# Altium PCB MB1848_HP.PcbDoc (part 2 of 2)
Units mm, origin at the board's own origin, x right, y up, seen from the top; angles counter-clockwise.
Board outline 61.5 x 34 mm, 4 copper layers (Top Layer, MidLayer 1, MidLayer 2, Bottom Layer), stack 1.035 mm thick; 124 components, 86 nets, 341 pads, 1082 vias.
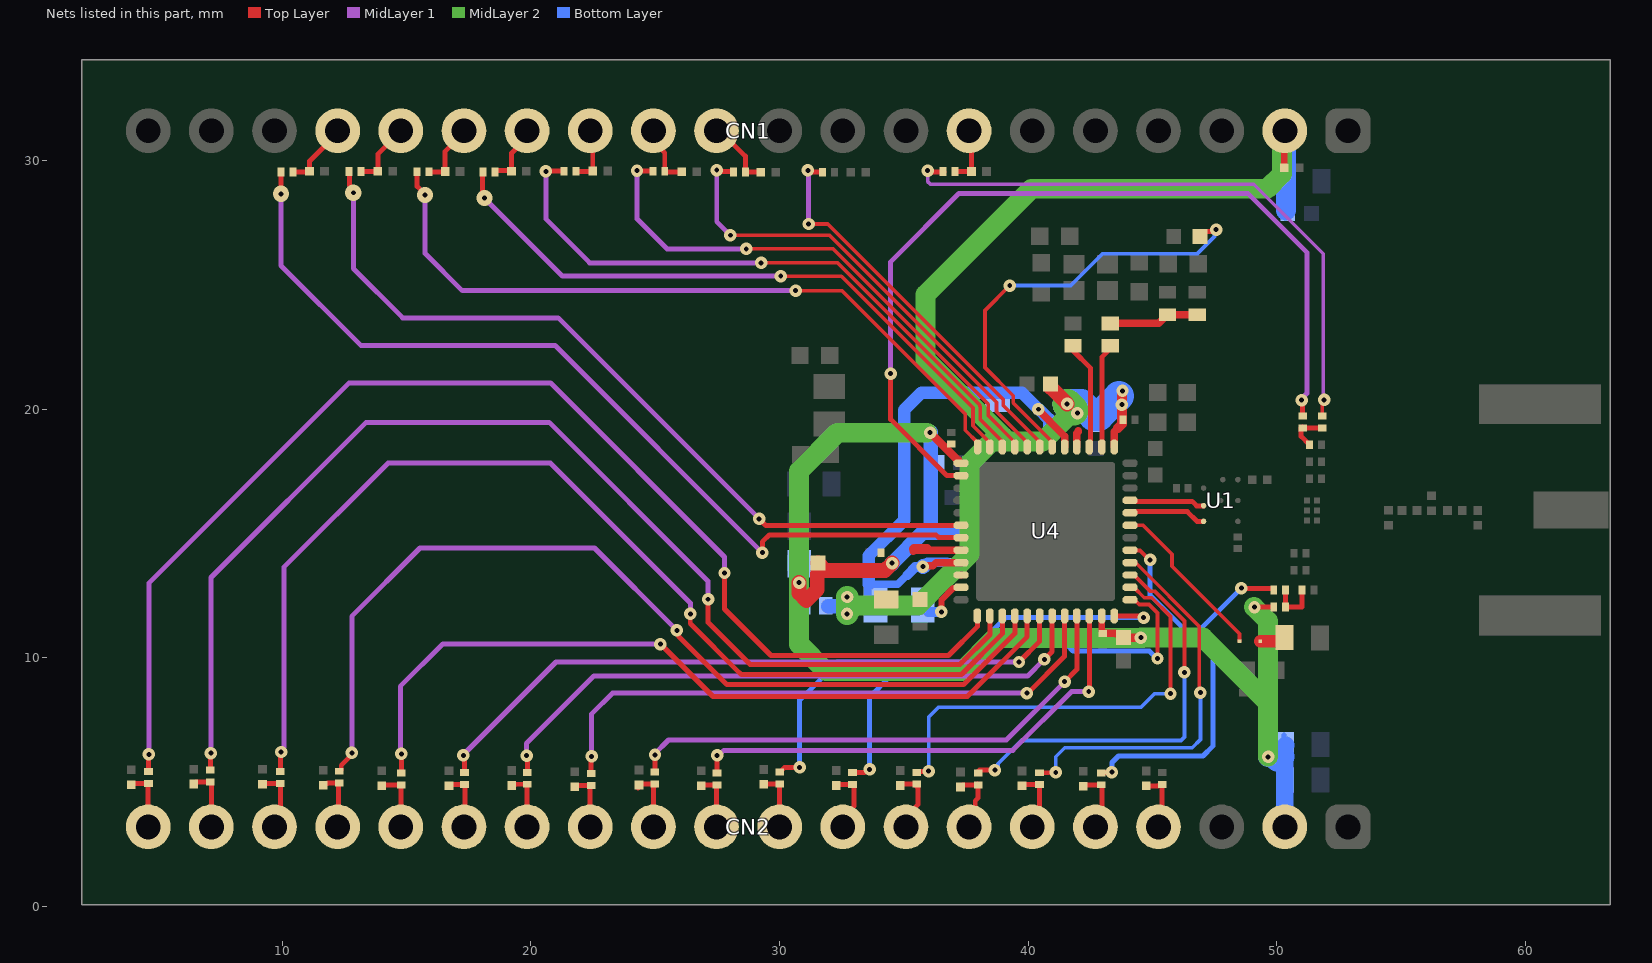
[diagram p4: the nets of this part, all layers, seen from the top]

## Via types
v1: diameter 0.5, hole 0.2, Top Layer to Bottom Layer, 395 vias
v2: diameter 0.65, hole 0.2, Top Layer to Bottom Layer, 321 vias
v3: diameter 0.6, hole 0.2, Top Layer to Bottom Layer, 291 vias
v4: diameter 0.4, hole 0.2, Top Layer to Bottom Layer, tented both sides, 75 vias

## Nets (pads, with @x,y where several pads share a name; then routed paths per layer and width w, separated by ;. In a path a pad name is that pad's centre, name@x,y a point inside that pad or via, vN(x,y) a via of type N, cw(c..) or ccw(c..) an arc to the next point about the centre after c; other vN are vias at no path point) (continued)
NetC202_1: C202.1 CN1.11 R202.2 | length 3.2
  Top Layer w0.2: CN1.11@27.413,31.109 27.683,31.109 28.62,30.172 R202.2@28.62,29.533 29.277,29.533 C202.1@29.284,29.526
  MidLayer 1 w0.2: CN1.11@27.463,30.896 CN1.11@27.463,31.192
NetC203_1: C203.1 CN1.12 R203.2 | length 3.1
  Top Layer w0.2: CN1.12@24.894,31.223 24.894,30.788 25.38,30.302 R203.2@25.38,29.568 ; R203.2@25.362,29.586 R203.2@25.38,29.568 ; R203.2@25.38,29.559 R203.2@25.38,29.568 ; C203.1@26.065,29.542 25.406,29.542 R203.2@25.38,29.568
  MidLayer 1 w0.2: CN1.12@24.923,30.718 CN1.12@24.923,31.192
NetC204_1: C204.1 CN1.13 R204.2 | length 2.3
  Top Layer w0.2: R204.2@21.814,29.563 22.502,29.563 C204.1@22.519,29.58 ; CN1.13@22.363,31.103 22.485,30.982 C204.1@22.485,29.577
NetC205_1: C205.1 CN1.14 R205.2 | length 2.5
  Top Layer w0.2: R205.2@18.552,29.537 18.552,29.544 18.592,29.584 C205.1@19.215,29.584 ; C205.1@19.215,29.563 C205.1@19.215,29.584 ; C205.1@19.253,29.584 C205.1@19.215,29.584 ; CN1.14@19.863,31.081 19.863,30.936 19.215,30.288 C205.1@19.215,29.584
NetC206_1: C206.1 CN1.15 R206.2 | length 2.5
  Top Layer w0.2: R206.2@15.89,29.539 16.536,29.539 C206.1@16.548,29.527 ; C206.1@16.547,29.55 16.547,30.367 CN1.15@17.285,31.104
NetC207_1: C207.1 CN1.16 R207.2 | length 2.7
  Top Layer w0.2: R207.2@13.163,29.55 13.877,29.55 C207.1@13.888,29.538 ; C207.1@13.838,29.558 13.838,30.249 CN1.16@14.717,31.127
  MidLayer 1 w0.2: CN1.16@14.763,31.192 CN1.16@14.813,31.142
NetC208_1: C208.1 CN1.17 R208.2 | length 2.7
  Top Layer w0.2: R208.2@10.426,29.532 11.131,29.532 C208.1@11.148,29.515 ; C208.1@11.093,29.558 11.093,29.967 CN1.17@12.196,31.07
NetC211_2: C211.2 CN1.7 R211.2 | length 2.5
  Top Layer w0.2: R211.2@37.06,29.553 C211.2@37.72,29.553 ; C211.2@37.722,29.553 CN1.7@37.722,31.115
  Top Layer w0.3: CN1.7@37.585,31.057 CN1.7@37.658,31.129 ; CN1.7@37.65,31.187 CN1.7@37.722,31.115 ; C211.2@37.72,29.553 C211.2@37.74,29.532
NetC212_1: C212.1 CN2.4 R212.2 | length 2.4
  Top Layer w0.2: C212.1@44.786,4.837 45.22,4.837 45.235,4.851 45.354,4.851 R212.2@45.394,4.891 ; CN2.4@45.243,3.192 45.39,3.339 R212.2@45.39,4.866
NetC213_1: C213.1 CN2.5 R213.2 | length 2.5
  Top Layer w0.2: C213.1@42.205,4.876 42.929,4.876 R213.2@42.939,4.886 ; CN2.5@42.703,3.192 42.964,3.453 R213.2@42.964,4.885
NetC214_1: C214.1 CN2.6 R214.2 | length 2.5
  Top Layer w0.2: C214.1@39.75,4.895 39.756,4.889 R214.2@40.452,4.889 ; CN2.6@40.163,3.192 40.451,3.48 R214.2@40.451,4.876
NetC215_1: C215.1 CN2.7 R215.2 | length 2.6
  Top Layer w0.2: C215.1@37.246,4.856 37.335,4.856 37.359,4.88 R215.2@37.977,4.88 ; CN2.7@37.623,3.192 37.87,3.439 37.87,4.242 37.977,4.35 R215.2@37.977,4.88 ; R215.2@37.957,4.915 37.977,4.895 R215.2@37.977,4.88 ; R215.2@37.985,4.88 R215.2@37.977,4.88
NetC216_1: C216.1 CN2.8 R216.2 | length 2.6
  Top Layer w0.2: C216.1@34.898,4.876 34.898,4.881 34.925,4.908 R216.2@35.512,4.908 ; CN2.8@35.083,3.192 35.083,3.609 35.571,4.096 35.571,4.749 R216.2@35.434,4.885
NetC217_1: C217.1 CN2.9 R217.2 | length 2.6
  Top Layer w0.2: C217.1@32.288,4.876 32.318,4.906 R217.2@32.934,4.906 ; CN2.9@32.543,3.192 32.543,3.572 32.999,4.028 32.999,4.866 R217.2@32.921,4.944
NetC218_1: C218.1 CN2.10 R218.2 | length 2.4
  Top Layer w0.2: C218.1@29.346,4.934 29.36,4.92 R218.2@30.012,4.92 ; R218.2@29.989,4.915 30.003,4.9 CN2.10@30.003,3.192
NetC219_1: C219.1 CN2.11 R219.2 | length 2.4
  Top Layer w0.2: C219.1@26.832,4.866 26.849,4.883 R219.2@27.481,4.883 ; CN2.11@27.463,3.192 27.463,4.843 27.486,4.866 R219.2@27.514,4.866
NetC220_1: C220.1 CN2.12 R220.2 | length 2.5
  Top Layer w0.2: C220.1@24.309,4.749 24.481,4.921 R220.2@24.981,4.921 ; CN2.12@24.923,3.192 24.923,4.881 24.927,4.885 R220.2@25.021,4.885
NetC221_1: C221.1 CN2.13 R221.2 | length 2.3
  Top Layer w0.2: C221.1@21.747,4.817 21.782,4.852 R221.2@22.423,4.852 ; CN2.13@22.383,3.192 22.383,4.839 R221.2@22.39,4.846
NetC222_1: C222.1 CN2.14 R222.2 | length 2.4
  Top Layer w0.2: C222.1@19.263,4.827 19.263,4.858 19.306,4.901 19.37,4.901 19.376,4.907 R222.2@19.851,4.907 ; R222.2@19.819,4.905 19.843,4.88 CN2.14@19.843,3.192
NetC223_1: C223.1 CN2.15 R223.2 | length 2.3
  Top Layer w0.2: C223.1@16.701,4.866 16.734,4.899 R223.2@17.324,4.899 ; CN2.15@17.303,3.192 17.344,3.233 R223.2@17.344,4.846
NetC224_1: C224.1 CN2.16 R224.2 | length 2.5
  Top Layer w0.2: C224.1@13.993,4.798 14.069,4.873 R224.2@14.785,4.873 ; CN2.16@14.763,3.192 14.763,4.833 14.805,4.876 R224.2@14.811,4.876
NetC225_1: C225.1 CN2.17 R225.2 | length 2.3
  Top Layer w0.2: C225.1@11.704,4.905 11.704,4.923 11.721,4.94 11.808,4.94 11.818,4.95 R225.2@12.259,4.95 ; CN2.17@12.259,3.228 R225.2@12.259,4.95 ; R225.2@12.293,4.95 R225.2@12.259,4.95
NetC226_1: C226.1 CN2.18 R226.2 | length 2.6
  Top Layer w0.2: C226.1@9.191,4.944 9.911,4.944 R226.2@9.915,4.939 ; CN2.18@9.683,3.192 9.921,3.43 R226.2@9.921,4.924
NetC227_1: C227.1 CN2.19 R227.2 | length 2.5
  Top Layer w0.2: C227.1@6.444,4.973 6.497,4.973 6.52,4.996 R227.2@7.101,4.996 ; R227.2@7.048,4.983 7.116,4.983 7.143,4.956 CN2.19@7.143,3.192
NetC228_1: C228.1 CN2.20 R228.2 | length 2.4
  Top Layer w0.2: C228.1@3.92,4.866 3.99,4.935 R228.2@4.612,4.935 ; CN2.20@4.603,3.192 R228.2@4.603,4.875
NetL2_2: L2.2 U4.47 | length 2.3
  Top Layer w0.25: v1(36.508,11.844) 36.508,12.317 36.992,12.8 37.279,12.8 U4.47@37.302,12.824
  Bottom Layer w0.4: L2.2@35.776,12.032 35.964,11.844 v1(36.508,11.844)
NetL9_2: L9.2 U4.30 | length 18.1
  Top Layer w0.15: v1(39.258,24.965) 38.26,23.967 38.26,21.665 39.394,20.531 39.394,20.247 40.961,18.68 U4.30@40.961,18.474
  Top Layer w0.2: L9.2@46.963,26.942 46.963,26.992 47.113,27.142 47.411,27.142 47.482,27.213 v1(47.563,27.213)
  Bottom Layer w0.15: v1(39.258,24.965) 41.71,24.965 42.995,26.25 46.811,26.25 47.496,26.934 47.496,27.146 v1(47.563,27.213)
NetR1_2: R1.2 SB11.1 | length 1
  Top Layer w0.5: SB11.1@49.328,10.661 50.172,10.661 R1.2@50.303,10.792
NetR2_2: R2.2 SB3.2 SB4.2 | length 2
  Top Layer w0.2: SB4.2@50.357,12.718 SB3.2@50.357,12.034 50.359,12.035 51.022,12.035 R2.2@51.022,12.72
NetR3_2: R3.2 SB6.2 SB9.2 | length 1.8
  Top Layer w0.2: SB6.2@51.041,19.24 SB6.2@50.986,19.24 ; SB6.2@51.041,19.27 SB6.2@51.029,19.283 ; R3.2@51.312,18.566 50.976,18.901 50.976,19.23 SB6.2@50.986,19.24 ; SB9.2@51.832,19.24 51.072,19.24 SB6.2@51.029,19.283 ; SB6.2@50.986,19.24 SB6.2@51.029,19.283
NetR100_1: R100.1 R101.1 SB13.2 | length 3.8
  Top Layer w0.2: SB13.2@43.303,23.442 SB13.2@43.403,23.542
  Top Layer w0.3: SB13.2@43.303,23.442 45.253,23.442 R101.1@45.603,23.792 R100.1@46.803,23.792
NetR201_1: R201.1 U4.31 | length 16.1
  Top Layer w0.15: v1(31.166,27.443) 31.939,27.443 38.998,20.383 38.998,20.139 40.461,18.676 U4.31@40.461,18.474
  Top Layer w0.2: v1(31.136,29.599) 31.217,29.599 31.291,29.525 R201.1@31.738,29.525
  MidLayer 1 w0.2: v1(31.136,29.599) 31.166,29.568 v1(31.166,27.443)
NetR202_1: R202.1 U4.32 | length 19.3
  Top Layer w0.15: v1(28.021,26.989) 32.01,26.989 38.728,20.271 38.728,19.888 39.961,18.655 U4.32@39.961,18.474
  Top Layer w0.2: v1(27.472,29.609) 27.553,29.609 27.615,29.548 R202.1@28.129,29.548
  MidLayer 1 w0.2: v1(27.472,29.609) 27.472,27.538 v1(28.021,26.989)
NetR203_1: R203.1 U4.33 | length 22
  Top Layer w0.15: v1(28.659,26.444) 32.148,26.444 38.32,20.271 38.32,20.268 38.391,20.197 38.391,19.734 39.461,18.663 U4.33@39.461,18.474
  Top Layer w0.2: v1(24.264,29.587) 24.283,29.568 R203.1@24.924,29.568
  MidLayer 1 w0.2: v1(24.264,29.587) 24.264,27.65 25.47,26.444 v1(28.659,26.444)
NetR204_1: R204.1 U4.34 | length 25.3
  Top Layer w0.15: v1(29.261,25.879) 32.33,25.879 38.05,20.159 38.05,20.107 38.07,20.088 38.07,19.576 U4.34@38.961,18.684
  Top Layer w0.2: v1(20.596,29.56) 20.61,29.574 R204.1@21.32,29.574 ; U4.34@38.961,18.474 U4.34@38.961,18.684
  MidLayer 1 w0.2: v1(20.596,29.56) 20.596,27.646 22.363,25.879 v1(29.261,25.879)
NetR205_1: R205.1 U4.35 | length 26.1
  Top Layer w0.15: v1(30.047,25.343) 32.485,25.343 37.78,20.047 37.78,19.324 38.461,18.643 U4.35@38.461,18.474
  Top Layer w0.2: R205.1@18.044,29.527 18.044,28.79 18.047,28.787 18.047,28.572 v2(18.133,28.486)
  MidLayer 1 w0.2: v2@18.128,28.48 21.266,25.343 v1(30.047,25.343)
NetR206_1: R206.1 U4.36 | length 29.3
  Top Layer w0.15: v1(30.648,24.76) 32.507,24.76 37.468,19.799 37.468,19.147 37.961,18.654 U4.36@37.961,18.474
  Top Layer w0.2: R206.1@15.419,29.515 15.419,28.956 15.742,28.633 v2(15.742,28.614)
  MidLayer 1 w0.2: v2(15.742,28.614) 15.742,26.255 17.237,24.76 v1(30.648,24.76)
NetR207_1: R207.1 U4.42 | length 32.8
  Top Layer w0.2: R207.1@12.691,29.55 12.691,28.982 12.853,28.82 v2(12.853,28.698) ; v1(29.18,15.58) 29.449,15.312 37.361,15.312 U4.42@37.404,15.354
  MidLayer 1 w0.2: v2(12.853,28.698) 12.853,25.653 14.838,23.669 21.092,23.669 v1(29.18,15.58)
NetR208_1: R208.1 U4.43 | length 36.6
  Top Layer w0.2: R208.1@9.928,29.55 9.939,29.538 v2(9.939,28.656) ; v1(29.307,14.219) 29.307,14.654 29.595,14.942 36.286,14.942 36.39,14.838 37.372,14.838 U4.43@37.396,14.862
  MidLayer 1 w0.2: v2@9.939,28.629 9.939,25.773 13.152,22.56 20.967,22.56 v1(29.307,14.219)
NetR211_1: R211.1 SB9.1 | length 24.8
  Top Layer w0.15: SB9.1@51.832,19.72 51.832,20.291 v1@51.901,20.36
  Top Layer w0.2: v1(35.955,29.592) 36.009,29.538 R211.1@36.619,29.538
  MidLayer 1 w0.15: v1@35.955,29.596 v1(35.955,29.592) 35.955,29.157 36.069,29.043 49.072,29.043 51.866,26.249 51.866,20.401 v1(51.901,20.366)
NetR213_1: R213.1 SB4.1 U4.17 | length 18.8
  Top Layer w0.15: U4.17@44.085,14.313 44.502,14.313 v1@44.883,13.932
  Top Layer w0.2: R213.1@42.939,5.366 42.955,5.381 43.352,5.381 v1(43.368,5.397) ; v1(48.575,12.794) 48.575,12.782 48.57,12.777 49.837,12.777 49.878,12.736 SB4.1@49.878,12.715
  Bottom Layer w0.2: v1(43.368,5.397) 43.368,5.779 43.629,6.04 47.031,6.04 47.429,6.439 47.429,9.988 46.599,10.818 ; 44.903,12.515 44.989,12.429 ; 44.903,12.535 v1(44.903,13.932) ; 45.003,12.415 46.599,10.818 ; v1(48.575,12.794) 46.599,10.818
NetR214_1: R214.1 U4.16 | length 15.7
  Top Layer w0.15: U4.16@44.099,13.824 44.317,13.824 U4.16@44.388,13.752 ; 44.427,13.714 46.883,11.257 v1@46.883,8.632
  Top Layer w0.2: R214.1@40.452,5.369 41.1,5.369 v1@41.133,5.402
  Bottom Layer w0.15: v1(41.108,5.385) 41.108,6.01 41.47,6.373 46.598,6.373 46.934,6.71 v1@46.934,8.54
  other v1: 46.923,8.592
NetR215_1: R215.1 U4.15 | length 16.6
  Top Layer w0.15: U4.15@44.099,13.324 44.25,13.324 44.899,12.675 45.081,12.675 46.283,11.473 v1(46.283,9.41)
  Top Layer w0.2: R215.1@37.977,5.421 38.032,5.476 v1(38.659,5.476)
  Bottom Layer w0.15: v1@38.706,5.413 38.786,5.493 38.786,5.729 39.724,6.667 42.077,6.667 42.079,6.669 46.148,6.669 46.283,6.804 v1(46.283,9.41)
NetR216_1: R216.1 U4.14 | length 18
  Top Layer w0.15: U4.14@44.099,12.824 44.25,12.824 44.669,12.405 44.97,12.405 45.723,11.651 v1(45.723,8.552)
  Top Layer w0.2: R216.1@35.512,5.388 35.536,5.413 35.97,5.413 v1(35.995,5.438)
  Bottom Layer w0.15: v1(35.995,5.438) 35.995,7.6 36.403,8.009 44.549,8.009 45.092,8.552 v1(45.723,8.552)
NetR217_1: R217.1 U4.13 | length 19.2
  Top Layer w0.15: U4.13@44.28,12.324 44.469,12.135 44.858,12.135 45.2,11.792 v1(45.2,9.963)
  Top Layer w0.2: R217.1@32.934,5.386 33.419,5.386 33.514,5.48 v1@33.593,5.48
  Bottom Layer w0.2: v1(33.623,5.508) 33.623,8.417 34.435,9.23 37.574,9.23 38.843,10.499 41.569,10.499 41.8,10.268 44.875,10.268 v1@45.196,9.947
NetR218_1: R218.1 U4.12 | length 20
  Top Layer w0.2: R218.1@30.012,5.4 30.047,5.4 30.087,5.44 30.087,5.47 30.204,5.587 v1@30.787,5.587 ; U4.12@43.461,11.677 44.492,11.677 44.559,11.61 v1(44.64,11.61)
  Bottom Layer w0.2: v1(30.805,5.583) 30.805,8.288 32.334,9.817 37.295,9.817 39.087,11.61 v1(44.64,11.61)
NetR219_1: R219.1 U4.10 | length 19.7
  Top Layer w0.2: R219.1@27.481,5.363 27.481,6.012 v1@27.485,6.015 ; v1@42.461,8.657 U4.10@42.461,11.677
  MidLayer 1 w0.2: v1(27.486,6.07) 27.556,6.07 27.754,6.268 39.382,6.268 41.745,8.63 v1(42.435,8.63)
NetR220_1: R220.1 U4.9 | length 21.3
  Top Layer w0.2: R220.1@24.981,5.401 v1@24.981,6.093 ; v1(41.466,9.032) 41.961,9.528 U4.9@41.961,11.677
  MidLayer 1 w0.2: v1@24.963,6.118 25.53,6.686 39.119,6.686 v1(41.466,9.032)
  other v1: 24.989,6.089
NetR221_1: R221.1 U4.8 | length 23.9
  Top Layer w0.2: R221.1@22.423,5.332 22.423,5.891 22.46,5.928 v1@22.507,5.928 ; v1@39.983,8.572 41.461,10.05 U4.8@41.461,11.677
  MidLayer 1 w0.2: v1(22.443,6.029) 22.443,7.739 23.276,8.572 v1(39.943,8.572)
NetR222_1: R222.1 U4.7 | length 25.4
  Top Layer w0.2: v1@19.789,6.123 19.851,6.061 R222.1@19.851,5.387 ; v1(40.651,9.933) 40.961,10.243 U4.7@40.961,11.677
  MidLayer 1 w0.2: v1@19.82,6.058 19.82,6.554 22.525,9.259 39.977,9.259 v1(40.651,9.933)
  other v1: 19.824,6.061
NetR223_1: R223.1 U4.6 | length 26.9
  Top Layer w0.2: v1@17.266,6.103 17.324,6.046 R223.1@17.324,5.379 ; v1(39.631,9.825) 40.463,10.657 U4.6@40.463,11.744
  MidLayer 1 w0.2: v1@17.264,6.082 21.007,9.825 v1@39.616,9.825
  other v1: 17.283,6.072
NetR224_1: R224.1 U4.5 | length 32.1
  Top Layer w0.2: v1@14.782,6.064 14.785,6.061 R224.1@14.785,5.353 ; v1(25.208,10.546) 27.318,8.435 37.55,8.435 39.956,10.842 U4.5@39.956,11.696
  MidLayer 1 w0.2: v1(14.784,6.128) 14.748,6.165 14.748,8.844 16.451,10.546 v1(25.208,10.546)
NetR225_1: R225.1 U4.4 | length 38
  Top Layer w0.2: R225.1@12.293,5.43 12.328,5.43 12.368,5.47 12.368,5.666 v1@12.814,6.113 ; v1@25.925,10.867 27.875,8.916 37.407,8.916 39.461,10.97 U4.4@39.461,11.677
  MidLayer 1 w0.2: v1(12.793,6.172) 12.793,11.664 15.538,14.409 22.555,14.409 v1(25.867,11.096)
  MidLayer 2 w0.2: v1@12.711,6.172 v1(12.793,6.172)
NetR226_1: R226.1 U4.3 | length 44.3
  Top Layer w0.2: v1@9.902,6.171 9.915,6.158 R226.1@9.915,5.419 ; v1(26.413,11.758) 26.406,11.751 26.406,11.373 28.402,9.378 28.46,9.319 37.314,9.319 37.337,9.341 38.961,10.965 U4.3@38.961,11.677
  MidLayer 1 w0.2: v1(9.952,6.203) 9.952,6.284 10.074,6.407 10.074,13.649 14.25,17.824 20.782,17.824 26.413,12.193 v1(26.413,11.758)
NetR227_1: R227.1 U4.2 | length 48
  Top Layer w0.2: R227.1@7.101,5.476 7.101,6.128 v1@7.164,6.191 ; v1(27.122,12.348) 27.122,11.417 28.756,9.783 28.815,9.724 37.253,9.724 38.461,10.933 U4.2@38.461,11.677
  MidLayer 1 w0.2: v1(7.126,6.156) 7.126,13.223 13.367,19.464 20.731,19.464 27.122,13.073 v1(27.122,12.348)
NetR228_1: R228.1 U4.1 | length 50.9
  Top Layer w0.2: R228.1@4.612,5.415 v1@4.612,6.103 ; v1(27.784,13.403) 27.784,11.956 29.655,10.085 36.794,10.085 37.954,11.245 U4.1@37.954,11.677
  MidLayer 1 w0.2: v1(4.628,6.11) 4.628,6.612 ; 4.644,6.612 4.644,13.008 12.688,21.053 20.782,21.053 27.784,14.051 v1(27.784,13.403)
NetSB6_1: SB6.1 U4.38 | length 35.7
  Top Layer w0.2: v1(34.465,21.42) 34.465,19.587 36.729,17.324 U4.38@37.302,17.324 ; v1(50.998,20.358) 51.041,20.315 SB6.1@51.041,19.72
  MidLayer 1 w0.2: v1(34.465,21.42) 34.465,25.922 37.218,28.675 48.834,28.675 51.207,26.302 51.207,20.625 50.998,20.417 v1(50.998,20.358)
NetSB11_2: SB11.2 U4.19 | length 6.8
  Top Layer w0.15: U4.19@44.099,15.324 44.614,15.324 45.783,14.155 45.783,13.679 48.503,10.959 SB11.2@48.503,10.661
NetSB13_1: SB13.1 U4.26 | length 4.1
  Top Layer w0.2: U4.26@42.961,18.474 42.961,22.089 SB13.1@43.303,22.431
NetSB15_1: SB15.1 U4.27 | length 4.2
  Top Layer w0.2: SB15.1@41.803,22.352 42.513,21.642 42.513,18.525 U4.27@42.461,18.474
RFI_N: U1.3 U4.21 | length 3
  Top Layer w0.2: U4.21@44.111,16.326 44.151,16.286 46.596,16.286 46.778,16.105 U1.3@47.055,16.105
RFI_P: U1.2 U4.20 | length 3.1
  Top Layer w0.2: U4.20@44.14,15.874 46.402,15.874 46.798,15.478 46.935,15.478 ; 46.937,15.475 U1.2@47.052,15.475
VDD: C1.2 C2.2 C3.2 C4.2 C5.2 C35.2 C39.1 C43.2 C44.2 CN2.2 L1.1 SB2.1 SB3.1 U4.11 U4.37 U4.44 | length 65.2
  Top Layer w0.2: v1@49.11,12.036 49.112,12.034 SB3.1@49.877,12.034
  Top Layer w0.254: C3.2@42.963,11.072 U4.11@42.963,11.635
  Top Layer w0.3: 35.373,14.279 35.418,14.324 ; 35.817,14.384 35.948,14.384 36.009,14.324 U4.44@37.302,14.324 ; C3.2@42.999,10.984 43.501,10.984 43.527,10.958 43.676,10.958 C2.2@43.826,10.808
  Top Layer w0.35: v1(36.052,19.052) 37.177,17.927 U4.37@37.177,17.849 ; C2.2@43.826,10.873 43.894,10.805 44.541,10.805 44.538,10.802 v1(44.531,10.802)
  Top Layer w0.4: 35.413,14.367 35.931,14.367
  Top Layer w0.6: v1(30.786,13.015) 30.786,12.589 31.077,12.298 31.514,12.735 31.514,13.372 ; C43.2@31.546,13.802 31.839,13.51 34.238,13.51 v1(34.527,13.799)
  MidLayer 2 w0.4: v1(49.647,6.008) v1@49.647,6.03
  MidLayer 2 w0.8: v1@35.927,19.043 32.322,19.043 30.786,17.507 v1(30.786,13.015) 30.786,10.537 31.868,9.456 37.335,9.456 38.676,10.797 v1@44.607,10.797 ; v1(44.531,10.802) 47.032,10.802 49.647,8.187 ; v1@49.079,12.038 49.647,11.469 49.647,8.187 ; v1@49.647,6.03 49.647,8.187
  MidLayer 2 w1.2: CN2.2@50.208,3.307 CN2.2@50.323,3.192
  Bottom Layer w0.2: C1.2@50.294,6.501 C1.2@50.294,6.894
  Bottom Layer w0.45: C4.2@36.955,15.035 C4.2@36.968,15.048
  Bottom Layer w0.6: v1@34.527,13.759 v1(34.527,13.799) 35.763,15.035 36.081,15.035 ; v1@36.081,19.052 36.081,17.848 36.081,15.035 ; C4.2@36.955,15.035 36.081,15.035
  Bottom Layer w0.7: CN2.2@50.323,3.192 50.323,6.446 C1.2@50.353,6.476
  Bottom Layer w0.8: L1.1@30.775,13.868 30.786,13.856 v1(30.786,13.015) SB2.1@30.786,12.14 ; v1(49.647,6.008) C1.2@50.088,6.008
  Bottom Layer w1.2: C1.2@50.088,6.008 C1.2@50.102,6.022
  other v1: 49.103,12.034
VDDPA: C10.1 C11.1 C17.1 C33.2 C40.1 C42.1 C110.1 C229.1 CN1.2 SB2.2 U4.25 U4.28 U4.46 | length 53.9
  Top Layer w0.25: C229.1@50.299,29.71 50.299,31.078 CN1.2@50.322,31.102
  Top Layer w0.3: U4.46@37.302,13.324 U4.46@37.312,13.324 ; U4.28@41.961,18.474 41.961,19.033 42.005,19.077 42.005,19.131 ; U4.25@43.461,18.474 43.461,19.09 43.608,19.236
  Top Layer w0.4: 43.608,19.236 43.766,19.394 v1(43.766,20.176) v1@43.766,20.743
  Top Layer w0.6: C17.1@40.901,20.99 40.901,20.873 v1(41.568,20.206)
  MidLayer 2 w0.8: v1(32.711,11.764) 33.041,12.094 35.572,12.094 37.646,14.168 37.646,17.804 38.535,18.693 40.584,18.693 v1@41.834,19.943 ; 39.128,18.748 35.873,22.003 35.873,24.599 40.133,28.859 49.613,28.859 50.208,29.454 CN1.2@50.208,31.077
  MidLayer 2 w0.9: v1(32.711,11.764) 32.715,11.768 v1(32.715,12.44)
  MidLayer 2 w1.2: v1@41.571,20.206 v1@41.834,19.943 ; CN1.2@50.208,31.077 CN1.2@50.323,31.192
  Bottom Layer w0.6: SB2.2@31.958,12.066 32.408,12.066 v1(32.711,11.764)
  Bottom Layer w0.8: v1(32.711,11.764) 32.722,11.775 32.722,12.432 v1(32.715,12.44) ; C40.1@50.363,27.986 CN1.2@50.363,31.152
  Bottom Layer w1.2: v1(41.568,20.206) 42.132,20.206 42.623,19.715 42.851,19.715 43.653,20.518
  other v1: 41.98,19.836 43.794,20.729
VDDRF1V55: C14.1 C34.2 C38.1 L2.1 U4.29 U4.45 | length 22.7
  Top Layer w0.3: v1(35.763,13.658) 35.801,13.696 36.163,13.696 36.291,13.824 U4.45@37.302,13.824 ; v1@40.341,20.027 41.461,18.906 U4.29@41.461,18.474
  Bottom Layer w0.3: L2.1@33.851,12.112 33.552,12.411 33.552,12.947 33.585,12.947 34.76,12.947 35.142,13.329 ; v1@35.712,13.658 v1(35.763,13.658) v1@35.817,13.658
  Bottom Layer w0.4: 35.142,13.329 35.451,13.639 35.744,13.639 v1(35.763,13.658) ; v1@35.782,13.677 35.942,13.837 C38.1@36.742,13.837
  Bottom Layer w0.5: 33.585,12.947 33.585,14.099 35.01,15.524 35.01,19.959 35.708,20.658 39.741,20.658 v1(40.409,19.99) 40.43,19.99 40.838,19.582 C34.2@40.838,19.287
  Bottom Layer w0.6: v1(35.763,13.658) v1@35.782,13.677
pads on no net: CN1.18 CN1.19 U4.22
copper on no net: | length 1444.2
  Top Layer w0.381: 96.493,4.727 106.905,4.727 130.52,4.727 159.722,4.727 176.228,4.727 190.702,4.727 ; 96.493,7.775 106.905,7.775 130.52,7.775 159.722,7.775 176.228,7.775 190.702,7.775 ; 96.493,10.823 106.905,10.823 130.52,10.823 159.722,10.823 176.228,10.823 190.702,10.823 ; 96.493,13.871 106.905,13.871 130.52,13.871 159.722,13.871 176.228,13.871 190.702,13.871 ; 96.493,16.919 106.905,16.919 130.52,16.919 159.722,16.919 176.228,16.919 190.702,16.919 ; 96.493,19.967 106.905,19.967 130.52,19.967 159.722,19.967 176.228,19.967 190.702,19.967 ; 96.493,23.015 106.905,23.015 130.52,23.015 159.722,23.015 176.228,23.015 190.702,23.015 ; 96.493,26.063 106.905,26.063 130.52,26.063 159.722,26.063 176.228,26.063 190.702,26.063 ; 96.493,29.111 106.905,29.111 130.52,29.111 159.722,29.111 176.228,29.111 190.702,29.111 ; 96.493,32.159 106.905,32.159 130.52,32.159 159.722,32.159 176.228,32.159 190.702,32.159 ; 96.493,35.207 190.702,35.207 ; 106.905,38.255 106.905,1.679 ; 130.52,38.255 130.52,1.679 ; 159.722,38.255 159.722,1.679 ; 176.228,38.255 176.228,1.679 ; 106.905,1.679 130.52,1.679 ; 106.905,1.679 96.493,1.679 96.493,38.255 190.702,38.255 190.702,1.679 176.228,1.679 ; 130.52,1.679 159.722,1.679 ; 159.722,1.679 176.228,1.679

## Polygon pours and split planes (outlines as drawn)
GND on MidLayer 1 "NONET_L-01_P-001" (solid, pour order 31): 1.954,0.029 63.452,0.029 63.452,34.029 1.954,34.029
GND on MidLayer 2 "TOP_LAYER_GND" (solid, remove dead copper, pour order 34): 1.891,34.097 63.388,34.097 63.388,0.097 1.891,0.097
GND on Bottom Layer "GND_L04_P035" (solid, remove dead copper, pour order 35): 1.978,34.101 63.475,34.101 63.475,0.101 1.978,0.101
GND on Top Layer "TOP_LAYER_GND" (solid, remove dead copper, pour order 30): 1.937,33.972 63.434,33.972 63.434,-0.028 1.937,-0.028

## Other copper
Top Layer:
  region net VDD: 34.979,14.02 35.318,14.02 ccw(c35.318,14.586) 35.718,14.186 35.413,14.367
  region net VDDPA: 32.724,12.804 34.881,12.804 ccw(c34.881,15.615) 36.142,13.102 36.722,13.393 cw(c37.048,12.745) 37.048,13.471 37.391,13.471 37.391,13.181 37.162,13.181 ccw(c37.161,12.624) 36.82,13.064 35.371,11.989 33.773,11.989 33.547,11.675 cw(c33.23,11.902) 33.23,11.512 32.706,11.512 cw(c32.706,11.661) 32.558,11.661 32.558,12.637 cw(c32.724,12.637)
  region net VDD: 31.245,11.887 30.68,11.887 cw(c30.68,12.141) 30.426,12.141 30.426,12.958 cw(c30.745,12.958) 30.745,13.277 31.439,13.277 cw(c31.439,12.967) 31.75,12.967 31.75,12.569 cw(c31.323,12.569) 31.625,12.268
  region net VDDPA: 41.806,18.772 41.806,19.207 ccw(c40.838,19.207) 41.523,19.892 41.355,20.059 cw(c41.475,20.179) 41.306,20.179 41.306,20.26 cw(c41.444,20.26) 41.346,20.358 41.421,20.433 cw(c41.502,20.352) 41.502,20.467 41.637,20.467 cw(c41.638,20.153) 41.86,20.375 42.191,20.044 cw(c42.072,19.925) 42.24,19.925 42.24,19.116 cw(c41.739,19.116) 42.177,18.872 42.121,18.772
  region net VDD: 36.537,18.721 36.537,18.595 37.081,18.051 37.081,18.721
  pour cut-out: 41.863,18.692 41.863,20.892 39.543,23.212 39.543,27.692 40.703,27.692 47.603,27.692 47.603,25.992 47.603,23.192 47.103,22.592 44.963,22.592 43.423,21.052 43.423,19.012 43.103,18.692
  pour cut-out: 44.873,18.925 44.86,18.938 44.672,19.056 44.672,19.139 44.86,19.327 46.909,19.327 46.909,18.938 44.873,18.938 44.848,18.964
  pour cut-out: 44.882,19.798 44.869,19.811 44.681,19.928 44.681,20.012 44.869,20.2 46.917,20.2 46.917,19.811 44.882,19.811 44.856,19.837
  pour cut-out: 43.96,19.832 44.16,19.832 44.166,19.838 44.166,19.283 44.014,19.283 43.96,19.337
  region net GND: 43.503,25.142 45.203,25.142 45.403,24.942 45.403,24.342 44.903,24.342 43.803,24.342 43.703,24.442 43.503,24.442
  pour cut-out: 31.343,20.372 32.643,20.372 32.643,19.872 31.343,19.872
  pour cut-out: 46.003,26.242 46.503,26.242 46.503,25.542 46.403,25.442 46.003,25.442
  pour cut-out: 46.203,27.342 46.603,27.342 46.603,26.542 46.203,26.542
  pour cut-out: 40.903,27.342 41.403,27.342 41.403,26.442 41.303,26.542 40.903,26.542
  pour cut-out: 49.266,9.954 49.328,9.892 49.703,9.892 49.703,9.092 49.203,9.092
  pour cut-out: 37.523,18.232 43.843,18.232 43.783,18.172 43.783,11.952 38.123,11.952 38.123,12.532 37.523,12.532
  region net VDD: 33.963,14.397 34.113,14.547 35.295,14.547 35.491,14.351 34.447,13.307 33.963,13.307
  pour cut-out: 63.522,14.138 59.043,14.138 59.043,17.665 63.522,17.665
  region net NetC28_2: 58.443,15.919 59.127,16.678 60.603,16.678 60.603,15.198 59.093,15.198
  pour cut-out: 45.16,17.299 47.516,17.299 47.516,15.012 45.16,15.012
  pour cut-out: 44.399,17.866 46.864,17.866 46.864,17.297 44.399,17.297
  region net NetC19_2: 49.012,17.013 48.858,17.013 48.426,17.158 48.858,17.303 49.012,17.303
  region net NetC25_1: 54.961,15.744 54.837,15.744 54.328,15.919 54.838,16.094 54.961,16.094
  region net NetC19_1: 49.711,17.333 49.83,17.333 50.166,17.076 49.801,16.983 49.711,16.983
  pour cut-out: 58.54,16.271 59.041,17.64 59.041,16.283 59.028,16.271
  pour cut-out: 58.54,15.564 59.053,15.564 59.053,14.138 58.528,15.576
  text "Layer" at 98.271,35.969 h1.52
  text "Name" at 108.683,35.969 h1.52
  text "Material" at 132.298,35.969 h1.52
  text "Thickness" at 161.5,35.969 h1.52
  text "Constant" at 178.006,35.969 h1.52
  text "Top Overlay" at 108.683,32.921 h1.52
  text "Top Solder" at 108.683,29.873 h1.52
  text "Solder Resist" at 132.298,29.873 h1.52
  text "0.39mil" at 161.5,29.873 h1.52
  text "3.5" at 178.006,29.873 h1.52
  text "1" at 98.271,26.825 h1.52
  text "Top Layer" at 108.683,26.825 h1.52
  text "1.38mil" at 161.5,26.825 h1.52
  text "Dielectric 2" at 108.683,23.777 h1.52
  text "1 x 2116 + 1 x 106" at 132.298,23.777 h1.52
  text "6.30mil" at 161.5,23.777 h1.52
  text "3.7" at 178.006,23.777 h1.52
  text "2" at 98.271,20.729 h1.52
  text "MidLayer 1" at 108.683,20.729 h1.52
  text "0.69mil" at 161.5,20.729 h1.52
  text "Dielectric 1" at 108.683,17.681 h1.52
  text "FR-4" at 132.298,17.681 h1.52
  text "24.02mil" at 161.5,17.681 h1.52
  text "5" at 178.006,17.681 h1.52
  text "3" at 98.271,14.633 h1.52
  text "MidLayer 2" at 108.683,14.633 h1.52
  text "0.69mil" at 161.5,14.633 h1.52
  text "Dielectric 3" at 108.683,11.585 h1.52
  text "1 x 2116 + 1 x 106" at 132.298,11.585 h1.52
  text "6.30mil" at 161.5,11.585 h1.52
  text "3.7" at 178.006,11.585 h1.52
  text "4" at 98.271,8.537 h1.52
  text "Bottom Layer" at 108.683,8.537 h1.52
  text "1.38mil" at 161.5,8.537 h1.52
  text "Bottom Solder" at 108.683,5.489 h1.52
  text "Solder Resist" at 132.298,5.489 h1.52
  text "0.39mil" at 161.5,5.489 h1.52
  text "3.5" at 178.006,5.489 h1.52
  text "Bottom Overlay" at 108.683,2.441 h1.52
  text ".Layer_Name" at 11.519,-19.394 h3
  text ".GTL" at 53.214,-19.394 h3
MidLayer 1:
  pour cut-out: 63.522,12.744 59.043,12.744 59.043,19.094 63.522,19.094
  pour cut-out: 41.913,18.655 41.913,20.855 39.593,23.175 39.593,27.655 40.753,27.655 47.653,27.655 47.653,25.955 47.653,23.155 47.153,22.555 45.013,22.555 43.473,21.015 43.473,18.975 43.153,18.655
Bottom Layer:
  pour cut-out: 35.837,19.228 35.851,19.215 35.811,19.175 35.811,15.203 35.187,15.203 35.133,15.256 35.133,19.228
  pour cut-out: 36.183,18.564 36.475,18.272 37.02,18.272 37.02,17.608 37.618,17.01 37.618,14.658 37.525,14.565 37.471,14.619 36.183,14.619
  pour cut-out: 40.202,20.566 40.261,20.624 40.261,20.636 41.686,20.636 41.697,20.624 41.745,20.624 43.205,19.164 43.205,18.788 40.461,18.788 40.449,18.776 40.19,19.035 40.19,20.554
  pour cut-out: 37.243,14.592 36.503,14.592 36.443,14.532 36.443,13.552 37.223,13.552 37.243,13.532
  pour cut-out: 34.383,12.712 35.183,12.712 35.183,11.312 34.383,11.312

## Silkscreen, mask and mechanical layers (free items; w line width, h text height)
Top Overlay:
  region: 7.124,23.189 7.124,10.213 16.773,10.213 16.773,23.189
  lines w0.15: 3.914,33.172 5.221,33.172 ; 4.068,33.51 5.068,33.51 ; 4.318,33.848 4.818,33.848 ; 4.563,32.16 4.563,33.17 ; 6.58,33.27 7.887,33.27 ; 6.734,33.608 7.734,33.608 ; 6.984,33.945 7.484,33.945 ; 7.229,32.257 7.229,33.268 ; 9.1,33.302 10.407,33.302 ; 9.254,33.64 10.254,33.64 ; 9.504,33.978 10.004,33.978 ; 9.749,32.29 9.749,33.3 ; 31.916,33.233 33.223,33.233 ; 32.07,33.57 33.07,33.57 ; 32.32,33.908 32.82,33.908 ; 32.565,32.22 32.565,33.23 ; 34.47,33.271 35.777,33.271 ; 34.623,33.608 35.623,33.609 ; 34.873,33.946 35.373,33.946 ; 35.119,32.258 35.119,33.269 ; 39.515,33.254 40.821,33.254 ; 39.668,33.592 40.668,33.592 ; 39.918,33.93 40.418,33.93 ; 40.163,32.242 40.163,33.252 ; 42.077,33.261 43.384,33.261 ; 42.23,33.598 43.23,33.598 ; 42.48,33.936 42.98,33.936 ; 42.726,32.248 42.726,33.259 ; 44.592,33.261 45.899,33.261 ; 44.746,33.598 45.746,33.598 ; 44.996,33.936 45.496,33.936 ; 45.241,32.248 45.241,33.259 ; 47.128,33.243 48.435,33.243 ; 47.239,5.119 48.546,5.119 ; 47.281,33.581 48.281,33.581 ; 47.393,5.457 48.393,5.457 ; 47.531,33.919 48.031,33.919 ; 47.643,5.794 48.143,5.794 ; 47.777,32.231 47.777,33.241 ; 47.888,4.106 47.888,5.117 ; 52.224,33.272 53.531,33.272 ; 52.227,5.119 53.534,5.119 ; 52.377,33.61 53.377,33.61 ; 52.38,5.457 53.38,5.457 ; 52.627,33.947 53.127,33.947 ; 52.63,5.794 53.13,5.794 ; 52.873,32.259 52.873,33.27 ; 52.876,4.106 52.876,5.117
  text "PA15" at 11.146,32.62 h1
  text "PA14" at 13.835,32.62 h1
  text "PA13" at 16.517,32.62 h1
  text "PA12" at 19.201,32.62 h1
  text "PA11" at 21.879,32.62 h1
  text "PA10" at 24.439,32.62 h1
  text "PB12" at 27.121,32.62 h1
  text "PB2" at 29.799,32.62 h1
  text "VDDRF" at 48.849,32.638 h1
  text "FeCTRL2" at 35.685,32.358 h1
  text "MB1848-LP" at 4.697,22.892 h2.5 r270
  text "Notes:" at 17.428,22.891 h1.2 r270
  text "PB3" at 3.788,1.116 h1
  text "PB4" at 6.347,1.119 h1
  text "PB5" at 8.904,1.119 h1
  text "PB6" at 11.468,1.117 h1
  text "PB7" at 14.027,1.119 h1
  text "PB8" at 16.586,1.117 h1
  text "PA0" at 19.147,1.117 h1
  text "PA1" at 21.704,1.116 h1
  text "PA2" at 24.139,1.116 h1
  text "PA3" at 26.692,1.116 h1
  text "PA4" at 29.251,1.119 h1
  text "PA5" at 31.808,1.119 h1
  text "PA6" at 34.372,1.117 h1
  text "PA7" at 36.931,1.119 h1
  text "PA8" at 39.491,1.117 h1
  text "PA9" at 42.051,1.117 h1
  text "NRST" at 44.118,1.123 h1
  text "VDD" at 49.571,1.08 h1
  text ".Layer_Name" at 11.519,-19.394 h3
  text ".GTO" at 53.214,-19.394 h3
Bottom Overlay:
  text "MB1848-LP" at 25.84,7.342 h2.5
Top Paste:
  lines w0.5: 12.743,26.712 cw(c14.593,26.712) 14.593,28.562 ; 12.752,9.144 12.752,26.644 ; 12.763,9.212 ccw(c14.613,9.212) 14.613,7.362 ; 14.583,7.332 51.483,7.332 ; 14.583,28.572 51.483,28.572 ; 51.493,28.582 cw(c51.493,26.732) 53.343,26.732 ; 51.533,7.342 ccw(c51.533,9.192) 53.383,9.192 53.383,17.689 ; 53.343,17.689 53.343,26.682
  text ".Layer_Name" at 11.519,-19.394 h3
  text ".GTP" at 53.214,-19.394 h3
Top Solder:
  lines w1.5: 53.328,17.416 53.328,19.142 53.328,26.448 ; 53.35,9.106 53.35,10.742 53.35,11.942 53.35,14.335 ; 53.352,9.154 cw(c51.502,9.154) 51.502,7.304 43.525,7.304 21.403,7.304 20.977,7.304 cw(c20.977,9.154) 19.127,9.154 19.127,11.942 19.127,22.742 19.127,26.654 cw(c20.977,26.654) 20.977,28.504 23.803,28.504 49.003,28.504 51.502,28.504 cw(c51.502,26.654) 53.352,26.654
  text ".Layer_Name" at 11.519,-19.394 h3
  text ".GTS" at 53.214,-19.394 h3
Mechanical 1:
  lines w0.3: 1.922,34.056 1.922,0.056 63.42,0.056 63.42,34.056 1.942,34.056
Top Assembly:
  text ".Layer_Name" at 11.519,-19.394 h3
  text ".GM2" at 53.214,-19.394 h3
Top Assembly (Mech14):
  rectangle: 46.85,16.963 47.129,17.305
  lines w0.1: 61.884,34.001 61.884,0.101 1.973,0.101 1.973,34.006 61.884,34.006
  text ".Layer_Name" at 11.519,-19.394 h3
  text ".GM14" at 53.214,-19.394 h3
Bottom Assembly (Mech15):
  lines w0.1: 61.884,34.006 61.884,0.106 1.973,0.106 1.973,34.011 61.884,34.011
Drill Drawing:
  lines w0.2: 3.696,80.186 33.446,80.186 ; 2.696,48.186 2.696,54.436 2.696,83.686 141.196,83.686 147.446,83.686 147.446,48.186 2.696,48.186 ; 3.446,49.436 3.446,51.936 5.946,51.936 5.946,49.436 3.446,49.436 ; 3.446,58.436 5.946,58.436 5.946,60.936 3.446,60.936 3.446,58.436 ; 41.946,58.436 41.946,60.936 44.446,60.936 44.446,58.436 41.946,58.436 ; 41.946,61.436 41.946,63.936 44.446,63.936 44.446,61.436 41.946,61.436 ; 41.946,64.436 41.946,66.936 44.446,66.936 44.446,64.436 41.946,64.436 ; 41.946,67.436 41.946,69.936 44.446,69.936 44.446,67.436 41.946,67.436 ; 41.946,70.436 41.946,72.936 44.446,72.936 44.446,70.436 41.946,70.436 ; 58.446,58.436 60.946,58.436 60.946,60.936 58.446,60.936 58.446,58.436 ; 58.446,61.436 60.946,61.436 60.946,63.936 58.446,63.936 58.446,61.436 ; 58.446,64.436 60.946,64.436 60.946,66.936 58.446,66.936 58.446,64.436 ; 58.446,67.436 60.946,67.436 60.946,69.936 58.446,69.936 58.446,67.436 ; 58.446,70.436 60.946,70.436 60.946,72.936 58.446,72.936 58.446,70.436 ; 58.446,76.436 58.446,78.936 60.946,78.936 60.946,76.436 58.446,76.436 ; 67.446,52.436 69.946,52.436 69.946,54.936 67.446,54.936 67.446,52.436 ; 76.696,67.436 76.696,69.936 79.196,69.936 79.196,67.436 76.696,67.436 ; 76.696,70.436 76.696,72.936 79.196,72.936 79.196,70.436 76.696,70.436 ; 76.696,76.436 79.196,76.436 79.196,78.936 76.696,78.936 76.696,76.436 ; 92.696,52.436 92.696,54.936 95.196,54.936 95.196,52.436 92.696,52.436 ; 92.696,61.436 92.696,63.936 95.196,63.936 95.196,61.436 92.696,61.436 ; 92.696,64.436 92.696,66.936 95.196,66.936 95.196,64.436 92.696,64.436 ; 92.696,70.436 92.696,72.936 95.196,72.936 95.196,70.436 92.696,70.436 ; 92.696,76.436 95.196,76.436 95.196,78.936 92.696,78.936 92.696,76.436
  lines w0.254: 4.994,96.727 6.688,96.727 5.841,95.034 4.994,96.727 ; 4.994,99.267 5.418,99.267 5.841,98.844 6.264,99.267 6.688,99.267 6.264,99.69 6.688,100.114 6.264,100.114 5.841,100.537 5.418,100.114 4.994,100.114 5.418,99.69 4.994,99.267
  lines w0.381: 3.476,93.891 182.548,93.891 ; 3.476,101.511 182.548,101.511 ; 17.468,90.081 17.468,105.321 ; 33.719,90.081 33.719,105.321 ; 61.397,90.081 61.397,105.321 ; 74.247,90.081 74.247,105.321 ; 92.885,90.081 92.885,105.321 ; 130.974,90.081 130.974,105.321 ; 145.956,90.081 145.956,105.321 ; 164.899,90.081 164.899,105.321 ; 3.476,90.081 182.548,90.081 182.548,105.321 3.476,105.321 3.476,90.081
  text "Symbol" at 5.762,102.654 h1.83
  text "Count" at 18.611,102.654 h1.83
  text "Hole Size" at 34.862,102.654 h1.83
  text "Plated" at 62.54,102.654 h1.83
  text "Hole Type" at 75.39,102.654 h1.83
  text "Drill Layer Pair" at 94.028,102.654 h1.83
  text "Via/Pad" at 132.117,102.654 h1.83
  text "Pad Shape" at 147.099,102.654 h1.83
  text "Template" at 166.042,102.654 h1.83
  text "40" at 18.611,98.844 h1.52
  text "39.37mil (1.000mm)" at 34.862,98.844 h1.52
  text "PTH" at 62.54,98.844 h1.52
  text "Round" at 75.39,98.844 h1.52
  text "Top Layer - Bottom Layer" at 94.028,98.844 h1.52
  text "Pad" at 132.117,98.844 h1.52
  text "(Mixed)" at 147.099,98.844 h1.52
  text "(Mixed)" at 166.042,98.844 h1.52
  text "1085" at 18.611,95.034 h1.52
  text "7.87mil (0.200mm)" at 34.862,95.034 h1.52
  text "PTH" at 62.54,95.034 h1.52
  text "Round" at 75.39,95.034 h1.52
  text "Top Layer - Bottom Layer" at 94.028,95.034 h1.52
  text "Via" at 132.117,95.034 h1.52
  text "Rounded" at 147.099,95.034 h1.52
  text "(Mixed)" at 166.042,95.034 h1.52
  text "1125 Total" at 18.611,91.224 h1.52
  text "PCB SPECIFICATIONS :" at 3.696,80.686 h3
  text "A.   MATERIAL :" at 3.696,76.686 h3
  text "FR-4" at 42.196,76.686 h3
  text "X  TG-170" at 58.696,76.686 h3
  text "TG-150" at 76.946,76.686 h3
  text "TG-140" at 92.946,76.686 h3
  text "B.   MATERIAL FAMILY :" at 3.696,73.686 h3
  text "N/A" at 42.196,73.686 h3
  text "C.   SOLDERMASK COLOR :" at 3.696,70.686 h3
  text "X   GREEN" at 42.196,70.686 h3
  text "BLUE" at 58.696,70.686 h3
  text "RED" at 76.946,70.686 h3
  text "BLACK" at 92.946,70.686 h3
  text "D.   SILKSCREEN COLOR :" at 3.696,67.686 h3
  text "X  WHITE" at 42.196,67.686 h3
  text "YELLOW" at 58.696,67.686 h3
  text "BLACK" at 76.946,67.686 h3
  text "E.   SURFACE FINISH :" at 3.696,64.686 h3
  text "X  ENIG" at 42.196,64.686 h3
  text "IMMERSION SILVER" at 58.696,64.686 h3
  text "IMMERSION TIN" at 92.946,64.686 h3
  text "HASL" at 42.196,61.686 h3
  text "HASL (PB-FREE)" at 58.696,61.686 h3
  text "GOLDEN FINGER" at 92.946,61.686 h3
  text "F.   IMPEDANCE CONTROL :" at 3.696,58.686 h3
  text "NO" at 42.196,58.686 h3
  text "X  YES  (SEE IMPEDANCE TABLE FOR DETAIL INFORMATION)" at 58.696,58.686 h3
  text "G.   THROUGH VIA :" at 3.696,55.686 h3
  text "PLUG THE VIAS WHICH ARE COVERED WITH SOLDERMASK ONE OR TWO SIDE." at 42.196,55.686 h3
  text "PLUG MATERIAL :" at 42.196,52.686 h3
  text "X  SOLDERMASK" at 67.696,52.686 h3
  text "NON-CONDUCTIVE EPOXY." at 92.946,52.686 h3
  text "H.   STACK-UP :" at 3.696,49.686 h3
  text "SEE LAYER STACK-UP SEQUENCE FOR OVERALL THICKNESS." at 42.196,49.686 h3
  text "mils" at 125.153,-15.678 h2.54
  text "mils" at 136.207,-15.678 h2.54
  text ".Layer_Name" at 11.519,-19.394 h3
  text ".DRL" at 53.214,-19.394 h3
Mechanical 20:
  circle w0.254: c89.523,-26.115 r1.3
  region: 75.045,-27.208 64.289,-27.208 65.282,-24.715 73.14,-24.715 73.589,-23.956 75.797,-26.504
  region: 89.048,-18.878 73.521,-18.878 72.827,-20.654 71.616,-21.878 70.219,-20.019 70.219,-18.368 71.362,-16.971 72.798,-16.592 89.048,-16.592
  lines w0.254: 65.282,-24.715 74.074,-24.715 71.008,-21.177 cw(c72.812,-19.233) 73.052,-16.592 89.816,-16.592 89.054,-18.878 ; 68.596,-16.345 cw(c71.022,-17.315) 71.259,-14.713 ; 68.635,-16.313 64.289,-27.208 83.612,-27.208 ccw(c83.86,-24.473) 86.409,-25.493 ; 70.375,-20.247 75.797,-26.504 ; 70.629,-20.247 75.934,-26.369 ; 70.629,-19.993 75.934,-26.115 ; 70.727,-18.878 83.72,-18.878 ; 70.756,-19.866 76.061,-25.988 ; 70.883,-19.739 76.188,-25.861 ; 71.01,-19.612 76.315,-25.734 ; 71.137,-19.485 76.442,-25.607 ; 71.192,-17.533 76.497,-23.654 ; 71.26,-14.713 90.71,-14.713 86.41,-25.491 ; 71.264,-19.358 76.515,-25.417 ; 71.264,-19.104 76.569,-25.226 ; 71.264,-18.85 76.569,-24.972 ; 71.264,-17.961 76.569,-24.083 ; 71.391,-18.723 76.696,-24.845 ; 71.391,-18.342 76.696,-24.464 ; 72.763,-24.728 ccw(c72.868,-24.193) 73.165,-23.736 ; 73.849,-18.865 ccw(c73.823,-19.432) 73.493,-19.894 75.858,-22.623 cw(c74.054,-24.567) 74.787,-27.115 ; 80.13,-27.004 83.02,-18.624 ; 80.353,-26.954 83.222,-18.633 ; 80.48,-26.954 83.349,-18.633 ; 80.734,-26.954 83.603,-18.633 ; 80.988,-26.954 83.857,-18.633 ; 81.242,-26.954 84.111,-18.633 ; 81.496,-26.954 84.365,-18.633 ; 81.75,-26.954 84.619,-18.633 ; 82.004,-26.954 84.873,-18.633 ; 82.258,-26.954 85.127,-18.633 ; 82.466,-27.004 85.356,-18.624 ; 85.356,-18.878 89.048,-18.878 ; 88.38,-18.876 89.142,-16.59 ; 88.546,-18.878 89.308,-16.592 ; 88.8,-18.878 89.562,-16.592
  lines w0.3: 2.519,-26.094 62.519,-26.094 ; 2.519,-21.094 62.519,-21.094 ; 2.519,-16.094 62.519,-16.094 ; 42.519,-31.094 42.519,-16.094 ; 62.519,-31.094 62.519,-11.094 ; 80.13,-27.004 82.466,-27.004 ; 2.519,-31.094 92.519,-31.094 92.519,-11.094 2.519,-11.094 2.519,-31.094
  text "Project: '.Board_Name'" at 3.519,-14.31 h3
  text "Layer:" at 3.519,-19.394 h3
  text "Gerber:" at 43.508,-19.394 h3
  text "Variant: '.VariantName'" at 3.519,-24.394 h3
  text "Ref: '.Board_Reference'" at 43.635,-24.394 h3
  text "R" at 89.015,-26.877 h1.52
  text "Date: '.Board_Document_Date'" at 3.519,-29.394 h3
  text "Rev: '.Board_PCB_Revision'" at 43.578,-29.394 h3

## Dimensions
2.008,34.082 to 63.498,34.082 on Mechanical 1
1.984,34.058 to 1.993,0.014 on Mechanical 1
